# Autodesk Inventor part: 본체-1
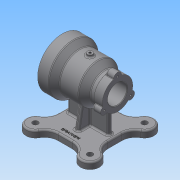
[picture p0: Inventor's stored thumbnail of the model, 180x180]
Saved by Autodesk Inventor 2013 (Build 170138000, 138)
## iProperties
Created: 2017-03
Part Number: 본체-1
Material: 일반
Document SubType Name: Modeling
Designer: Administrator
Density: 1 g/cm^3
Author: Administrator
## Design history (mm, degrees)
sketch "스케치1"
  geometry: L1 (-50, 0)-(50, 0); L2 (-50, 35)-(-27, 35); L3 (-27, 35)-(-27, 26); L4 (-27, 26)-(20, 26); L5 (20, 26)-(20, 17.5); L6 (20, 17.5)-(50, 17.5); L7 (50, 17.5)-(50, 27.5); L8 (50, 27.5)-(35, 27.5); L9 (15, 36)-(-19, 36); L10 (-19, 36)-(-30, 45); L11 (-30, 45)-(-50, 45); L12 (-50, 45)-(-50, 35); L13 (15, 36)-(27, 26.182); L14 (27, 26.182)-(35, 26.182); L15 (35, 26.182)-(35, 27.5); 2 further points
  constraints: 30 end point, 9 parallel, 3 perpendicular, 2 vertical alignment, 1 coincident, 1 horizontal, 1 midpoint, 1 vertical
  dimensions: "d0" = 100 distance of L1.start L1.end; "d2" = 20 distance of L10.end L11.end; "d3" = 31 distance from line of L9.end L12; "d6" = 65 distance from line of L9.start L12; "d8" = 70 diameter of L2 L1; "d9" = 52 diameter of L4 L1; "d10" = 35 diameter of L6 L1; "d11" = 23 distance of L2.start L2.end; "d12" = 47 distance of L3.end L4.end; "d13" = 90 diameter of L11 L1; "d17" = 55 diameter of L8 L1; "d18" = 72 diameter of L9 L1; "d19" = 23 distance from line of L13.end L7; "d20" = 15 distance of L7.end L8.end
revolve "회전1" sketch "스케치1" stored, may be unused: angle "d21" = 90 deg
node "작업 평면1"
sketch "스케치2"
  geometry: L1 (-45, 45)-(45, 45); L2 (45, 45)-(45, -45); L3 (45, -45)-(-45, -45); L4 (-45, -45)-(-45, 45); L5 (-45, 45)-(45, -45); L6 (45, 45)-(-45, -45); L7 (-45, -33.103)-(-45, 33.103); L8 (45, 33.103)-(45, -33.103); L9 (-33.103, 45)-(33.103, 45); L10 (-33.103, -45)-(33.103, -45); A1 r 70 centre (0, 0) between (-49.497, 49.497) and (49.497, 49.497); A2 r 17 centre (-49.497, 49.497) between (-45, 33.103) and (-33.103, 45); A3 r 17 centre (49.497, 49.497) between (45, 33.103) and (33.103, 45); A4 r 17 centre (-49.497, -49.497) between (-45, -33.103) and (-33.103, -45); A5 r 17 centre (49.497, -49.497) between (45, -33.103) and (33.103, -45); 3 further points
  constraints: 20 end point, 12 point on circle, 8 point on line, 5 centre point, 5 coincident, 3 equal radius, 2 horizontal alignment, 2 midpoint, 2 parallel, 2 perpendicular, 2 vertical alignment, 1 horizontal
  dimensions: "d23" = 140 diameter of A1; "d26" = 90 distance of L1.start L1.end; "d27" = 90 deg dimension on point (0, 0) A1.start point (-49.497, -49.497); "d28" = 34 diameter of A2
extrude "돌출1" join sketch "스케치2" distance "d29" = 12; taper "d30" = 0 deg
fillet "모깎기1" dims "d35" = 25
node "작업 평면2"
sketch "스케치5"
  geometry: C1 r 5 at (0, 0); 1 further point
  constraints: 1 centre point, 1 coincident
  dimensions: "d37" = 10 diameter of C1
extrude "돌출2" join sketch "스케치5" stored distance "d39" = 74; taper "d40" = 0 deg
sketch "스케치6"
  geometry: C1 r 5 at (0, 0) reference; 1 further point
  constraints: 1 coincident
hole "구멍1" sketch "스케치6" at (0, 0) diameter "d41" = 4.134; stored, may be unused: countersink angle "d45" = 90 deg, drill point angle "d47" = 118 deg; dims "d42" = 6, "d43" = 4, "d44" = 2, "d46" = 8
sketch "스케치8"
  geometry: C1 r 5 at (-49.497, 49.497); C2 r 5 at (49.497, 49.497); C3 r 5 at (-49.497, -49.497); C4 r 5 at (49.497, -49.497); A1 r 17 centre (-49.497, 49.497) between (-34.661, 57.796) and (-57.796, 34.661) reference; A2 r 17 centre (-49.497, -49.497) between (-57.796, -34.661) and (-34.661, -57.796) reference; A3 r 17 centre (49.497, -49.497) between (34.661, -57.796) and (57.796, -34.661) reference; A4 r 17 centre (49.497, 49.497) between (57.796, 34.661) and (34.661, 57.796) reference; 1 further point
  constraints: 4 centre point, 4 coincident, 3 equal radius
  dimensions: "d60" = 10 diameter of C1
extrude "돌출3" cut sketch "스케치8" stored distance "d62" = 74; taper "d63" = 0 deg
sketch "스케치9"
  geometry: C1 r 17.5 at (0, 0) reference; A1 r 27.5 centre (0, 0) between (-27.5, 0) and (-26.609, -6.943) reference; A2 r 7 centre (-27.5, 0) between (-26.609, 6.943) and (-26.609, -6.943)
  constraints: 5 point on circle, 1 centre point, 1 horizontal alignment
  dimensions: "d64" = 14 diameter of A2
extrude "돌출4" join sketch "스케치9" distance "d66" = 15; taper "d67" = 0 deg
sketch "스케치10"
  geometry: A1 r 7 centre (0, 0) between (0.891, 6.943) and (0.891, -6.943) reference; 1 further point
  constraints: 1 coincident
hole "구멍3" sketch "스케치10" at (0, 0) diameter "d68" = 3.242; stored, may be unused: countersink angle "d72" = 90 deg, drill point angle "d74" = 118 deg; dims "d69" = 9, "d70" = 4, "d71" = 2, "d73" = 11
sketch "스케치11"
  geometry: L1 (12.842, -70)-(-12.842, -70) reference; L2 (-12.842, -70)-(-34.661, -70) reference; L3 (-34.661, -70)-(-66.497, -70) reference; L4 (34.661, -70)-(12.842, -70) reference; L5 (66.497, -70)-(34.661, -70) reference; L6 (-18.14, -31.096)-(-25, -70); L7 (0, 0)-(0, -70); L8 (0, -36)-(0, -70); A1 r 36 centre (0, 0) between (-18.14, -31.096) and (0, -36) reference; 3 further points
  constraints: 6 end point, 2 point on circle, 2 point on line, 1 collinear, 1 midpoint
  dimensions: "d78" = 100 deg angle of L6 L3; "d79" = 25 horizontal distance of L6.end point (0, 0)
extrude "돌출5" join sketch "스케치11" stored distance "d80" = 8; taper "d81" = 0 deg
chamfer "모따기1" distance "d86" = 1; stored, may be unused: second distance "d87" = 2, angle "d88" = 45 deg
fillet "모깎기3" dims "d89" = 3
sketch "스케치13"
  geometry: L1 (29.226, -44.367)-(19.774, -36.633) reference; L2 (18, -36)-(-14, -36) reference; L3 (4, -70)-(4, -31.096) reference; L4 (19.774, -36.633)-(18, -36) reference; L5 (50, -45)-(31, -45) reference; L6 (37.279, -70)-(12.842, -70) reference; L7 (37.279, -70)-(63.497, -70) reference; L8 (31, -45)-(29.226, -44.367) reference; L9 (37, -45)-(37, -70); 2 further points
  constraints: 2 end point, 2 point on line, 1 vertical
  dimensions: "d94" = 37 distance from line of L9 point (0, 0)
feature "리브1" sketch "스케치13" dims "d95" = 1, "d96" = 8, "d97" = 0, "d98" = 0, "d99" = 1, "d100" = 1
fillet "모깎기4" dims "d101" = 3
fillet "모깎기5" dims "d102" = 3
fillet "모깎기6" dims "d103" = 3
sketch "스케치14" dims "d104" = 80
  geometry: C1 r 36 at (0, 0) reference; 1 further point
  constraints: 2 horizontal alignment, 2 other
hole "구멍4" sketch "스케치14" at (40, 0) diameter "d106" = 3.242; stored, may be unused: countersink angle "d110" = 90 deg, drill point angle "d112" = 118 deg; dims "d107" = 9, "d108" = 4, "d109" = 2, "d111" = 11
fillet "모깎기7" dims "d116" = 3
fillet "모깎기8" dims "d117" = 1, "d118" = 3
fillet "모깎기9" dims "d119" = 3
sketch "스케치15"
  geometry: L1 (45, -12.842)-(45, 12.842) reference; 2 further points
  constraints: 1 other
  dimensions: "d120" = 35 distance of point (0, -35) point (0, 0); "d121" = 45 distance from line of point (0, -35) L1
feature "엠보싱1" sketch "스케치15" dims "d0" = 100, "d2" = 20, "d3" = 31, "d6" = 65, "d8" = 70, "d9" = 52, "d10" = 35, "d11" = 23, "d12" = 47, "d13" = 90, "d17" = 55, "d18" = 72, "d19" = 23, "d20" = 15, "d23" = 140, "d26" = 90, "d27" = 90 deg, "d28" = 34, "d122" = 0.5, "d123" = 0
fillet "모깎기10" dims "d124" = 1
node "솔리드1"
pattern_circular "원형 패턴2" dims angle "d76" = 360 deg
mirror "대칭1"
mirror "대칭2"
pattern_circular "원형 패턴3" dims angle "d114" = 360 deg
other parameters: "d22" = -82
